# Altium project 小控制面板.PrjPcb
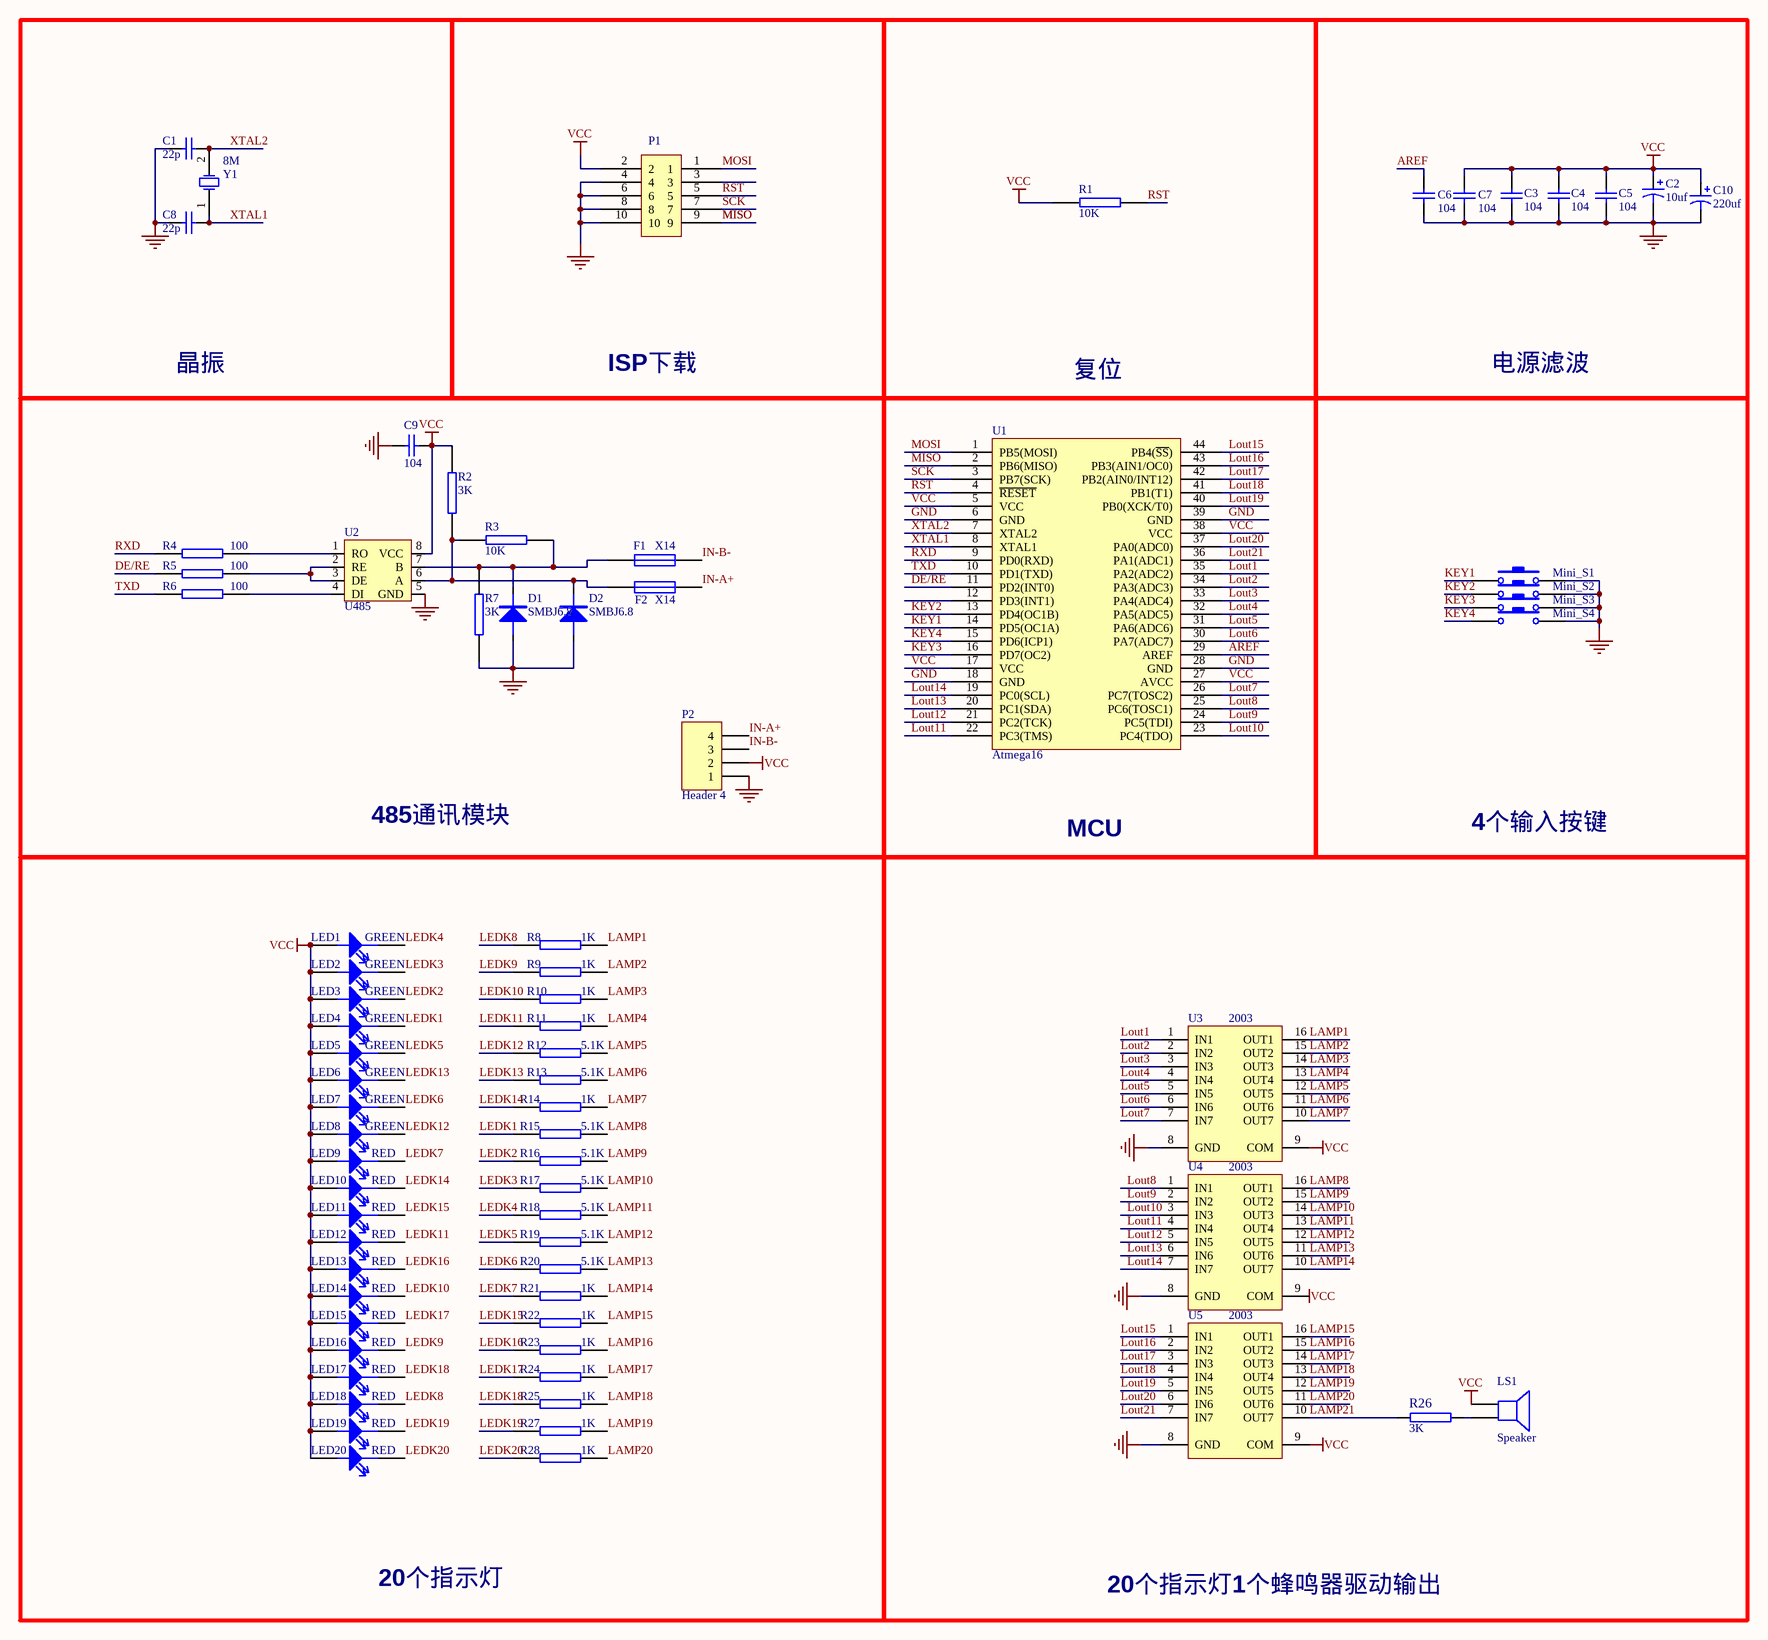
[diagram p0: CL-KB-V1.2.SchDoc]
1 sheet, 75 parts. Net scope: global (net labels, ports and power ports of the same name join across sheets).
Board file: CL-KB-V1.2.pcbdoc

## Sheet CL-KB-V1.2.SchDoc
size A2

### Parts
C1  22p  [c0805c]
C2  10uf  [E6.5MM]
C3  104  [c0805c]
C4  104  [c0805c]
C5  104  [c0805c]
C6  104  [c0805c]
C7  104  [c0805c]
C8  22p  [c0805c]
C9  104  [c0805c]
C10  220uf  [E6.5MM]
D1  SMBJ6.8  [SMBJ_SMT]
D2  SMBJ6.8  [SMBJ_SMT]
F1  X14  [PPTC_SMT]
F2  X14  [PPTC_SMT]
LED1  GREEN  [PLED10*10]
LED2  GREEN  [PLED10*10]
LED3  GREEN  [PLED10*10]
LED4  GREEN  [PLED10*10]
LED5  GREEN  [PLED10*10]
LED6  GREEN  [PLED10*10]
LED7  GREEN  [PLED10*10]
LED8  GREEN  [PLED10*10]
LED9  RED  [PLED10*10]
LED10  RED  [PLED10*10]
LED11  RED  [PLED10*10]
LED12  RED  [PLED10*10]
LED13  RED  [PLED10*10]
LED14  RED  [PLED10*10]
LED15  RED  [PLED10*10]
LED16  RED  [PLED10*10]
LED17  RED  [PLED10*10]
LED18  RED  [PLED10*10]
LED19  RED  [PLED10*10]
LED20  RED  [PLED10*10]
LS1  Speaker  [SPK]
Mini_S1  (no value)  [KEYL]
Mini_S2  (no value)  [KEYL]
Mini_S3  (no value)  [KEYL]
Mini_S4  (no value)  [KEYL]
P1  CON10  [ISP]  (value not drawn)
P2  Header 4  [C3-4L]
R1  10K  [0805C]
R2  3K  [0805C]
R3  10K  [0805C]
R4  100  [0805C]
R5  100  [0805C]
R6  100  [0805C]
R7  3K  [0805C]
R8  1K  [0805C]
R9  1K  [0805C]
R10  1K  [0805C]
R11  1K  [0805C]
R12  5.1K  [0805C]
R13  5.1K  [0805C]
R14  1K  [0805C]
R15  5.1K  [0805C]
R16  5.1K  [0805C]
R17  5.1K  [0805C]
R18  5.1K  [0805C]
R19  5.1K  [0805C]
R20  5.1K  [0805C]
R21  1K  [0805C]
R22  1K  [0805C]
R23  1K  [0805C]
R24  1K  [0805C]
R25  1K  [0805C]
R26  3K  [0805C]
R27  1K  [0805C]
R28  1K  [0805C]
U1  Atmega16  [QFP44]
U2  U485  [SOP8]
U3  2003  [SO_16]
U4  2003  [SO_16]
U5  2003  [SO_16]
Y1  8M  [XTP2]

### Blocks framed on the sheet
晶振: C1 C8 Y1
ISP下载: P1
复位: R1
电源滤波: C2-C7 C10
485通讯模块: C9 D1 D2 F1 F2 P2 R2-R7 U2
MCU: U1
4个输入按键: Mini_S1-Mini_S4
20个指示灯: LED1-LED20 R8-R25 R27 R28
20个指示灯1个蜂鸣器驱动输出: LS1 R26 U3-U5

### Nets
GND: C1.2 C2.2 C3.1 C4.1 C5.2 C6.1 C7.1 C8.2 C9.2 C10.2 D1.A D2.A Mini_S1.2 Mini_S2.2 Mini_S3.2 Mini_S4.2 P1.4 P1.6 P1.8 P1.10 P2.1 R7.1 U1.6(GND) U1.18(GND) U1.28(GND) U1.39(GND) U2.5(GND) U3.8(GND) U4.8(GND) U5.8(GND)
VCC: C2.1 C3.2 C4.2 C5.1 C7.2 C9.1 C10.1 LED1.A LED2.A LED3.A LED4.A LED5.A LED6.A LED7.A LED8.A LED9.A LED10.A LED11.A LED12.A LED13.A LED14.A LED15.A LED16.A LED17.A LED18.A LED19.A LED20.A LS1.1 P1.2 P2.2 R1.2 R2.1 U1.5(VCC) U1.17(VCC) U1.27(AVCC) U1.38(VCC) U2.8(VCC) U3.9(COM) U4.9(COM) U5.9(COM)
AREF: C6.2 U1.29(AREF)
DE/RE: R5.2 U1.11(PD2(INT0))
IN-A+: F2.1 P2.4
IN-B-: F1.1 P2.3
KEY1: Mini_S1.1 U1.14(PD5(OC1A))
KEY2: Mini_S2.1 U1.13(PD4(OC1B))
KEY3: Mini_S3.1 U1.16(PD7(OC2))
KEY4: Mini_S4.1 U1.15(PD6(ICP1))
LAMP1: R8.2 U3.16(OUT1)
LAMP2: R9.2 U3.15(OUT2)
LAMP3: R10.2 U3.14(OUT3)
LAMP4: R11.2 U3.13(OUT4)
LAMP5: R12.2 U3.12(OUT5)
LAMP6: R13.2 U3.11(OUT6)
LAMP7: R14.2 U3.10(OUT7)
LAMP8: R15.2 U4.16(OUT1)
LAMP9: R16.2 U4.15(OUT2)
LAMP10: R17.2 U4.14(OUT3)
LAMP11: R18.2 U4.13(OUT4)
LAMP12: R19.2 U4.12(OUT5)
LAMP13: R20.2 U4.11(OUT6)
LAMP14: R21.2 U4.10(OUT7)
LAMP15: R22.2 U5.16(OUT1)
LAMP16: R23.2 U5.15(OUT2)
LAMP17: R24.2 U5.14(OUT3)
LAMP18: R25.2 U5.13(OUT4)
LAMP19: R27.2 U5.12(OUT5)
LAMP20: R28.2 U5.11(OUT6)
LAMP21: R26.1 U5.10(OUT7)
LEDK1: LED4.K R15.1
LEDK2: LED3.K R16.1
LEDK3: LED2.K R17.1
LEDK4: LED1.K R18.1
LEDK5: LED5.K R19.1
LEDK6: LED7.K R20.1
LEDK7: LED9.K R21.1
LEDK8: LED18.K R8.1
LEDK9: LED16.K R9.1
LEDK10: LED14.K R10.1
LEDK11: LED12.K R11.1
LEDK12: LED8.K R12.1
LEDK13: LED6.K R13.1
LEDK14: LED10.K R14.1
LEDK15: LED11.K R22.1
LEDK16: LED13.K R23.1
LEDK17: LED15.K R24.1
LEDK18: LED17.K R25.1
LEDK19: LED19.K R27.1
LEDK20: LED20.K R28.1
Lout1: U1.35(PA2(ADC2)) U3.1(IN1)
Lout2: U1.34(PA3(ADC3)) U3.2(IN2)
Lout3: U1.33(PA4(ADC4)) U3.3(IN3)
Lout4: U1.32(PA5(ADC5)) U3.4(IN4)
Lout5: U1.31(PA6(ADC6)) U3.5(IN5)
Lout6: U1.30(PA7(ADC7)) U3.6(IN6)
Lout7: U1.26(PC7(TOSC2)) U3.7(IN7)
Lout8: U1.25(PC6(TOSC1)) U4.1(IN1)
Lout9: U1.24(PC5(TDI)) U4.2(IN2)
Lout10: U1.23(PC4(TDO)) U4.3(IN3)
Lout11: U1.22(PC3(TMS)) U4.4(IN4)
Lout12: U1.21(PC2(TCK)) U4.5(IN5)
Lout13: U1.20(PC1(SDA)) U4.6(IN6)
Lout14: U1.19(PC0(SCL)) U4.7(IN7)
Lout15: U1.44(PB4(~{SS})) U5.1(IN1)
Lout16: U1.43(PB3(AIN1/OC0)) U5.2(IN2)
Lout17: U1.42(PB2(AIN0/INT12)) U5.3(IN3)
Lout18: U1.41(PB1(T1)) U5.4(IN4)
Lout19: U1.40(PB0(XCK/T0)) U5.5(IN5)
Lout20: U1.37(PA0(ADC0)) U5.6(IN6)
Lout21: U1.36(PA1(ADC1)) U5.7(IN7)
MISO: P1.9 U1.2(PB6(MISO))
MOSI: P1.1 U1.1(PB5(MOSI))
RST: P1.5 R1.1 U1.4(~{RESET})
RXD: R4.2 U1.9(PD0(RXD))
SCK: P1.7 U1.3(PB7(SCK))
TXD: R6.2 U1.10(PD1(TXD))
XTAL1: C8.1 U1.8(XTAL1) Y1.1(OSC1)
XTAL2: C1.1 U1.7(XTAL2) Y1.2(OSC2)
NetD1_K: D1.K F1.2 R3.1 R7.2 U2.7(B)
NetD2_K: D2.K F2.2 R2.2 R3.2 U2.6(A)
NetLS1_2: LS1.2 R26.2
NetR4_1: R4.1 U2.1(RO)
NetR5_1: R5.1 U2.2(RE) U2.3(DE)
NetR6_1: R6.1 U2.4(DI)

Not connected (* = marked no-connect by the designer): P1 3; U1 12(PD3(INT1))

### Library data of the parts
C1 C3-C9 = Cap: Capacitor
C2 = Cap Pol1: Polarized Capacitor (Radial)
C10 = Cap Pol1: Polarized Capacitor (Radial); Value: 10uf
D1 D2 = DIODE
F1 F2 = Fuse 1: Fuse
LED1-LED20 = LED: Zener Diode
LS1 = Speaker: Loudspeaker
Mini_S1-Mini_S4 = SW-PB: Switch
P1 = SPI10
P2 = Header 4: Header, 4-Pin
R1-R28 = RES2
U3-U5 = ULN2003A: High-Voltage, High-Current Darlington Array
Y1 = XTAL: Crystal Oscillator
